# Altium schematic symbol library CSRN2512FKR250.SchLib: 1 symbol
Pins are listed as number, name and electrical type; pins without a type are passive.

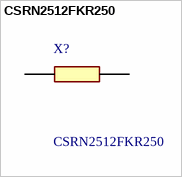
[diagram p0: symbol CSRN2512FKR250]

## CSRN2512FKR250
designator X?
RES CS, 2512, 0.25 ohm, 1%, 2W; Manufacturer_Name: Stackpole Electronics, Inc.; Geometry.Height: 0.7mm
footprint RESC6432X70N
pins: 1, 2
